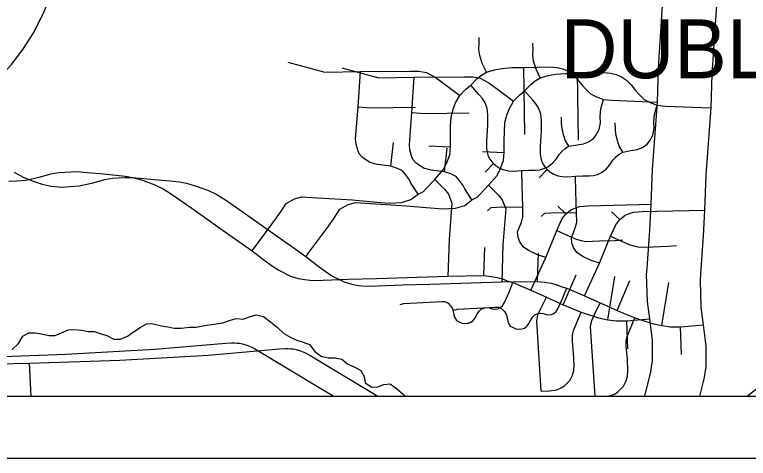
# Model space of a CAD drawing. Extents: x -38.2 to 41.9, y -4 to 24.9.
# Drawn here: x 3.113 to 4.294, y 14 to 14.713 of the extents above; entities that cross this region are included whole.
import ezdxf

# ---------------------------------------------------------------- set-up
doc = ezdxf.new("R2010")
doc.units = 0
for name, color, linetype in [('Default', 7, 'Continuous'), ('GM_X_City_Street', 7, 'Continuous'), ('GM_X_Corporation_Text', 7, 'Continuous'), ('GM_X_County_Road', 7, 'Continuous'), ('GM_X_Interchange_Ramps', 7, 'Continuous'), ('GM_X_Interstate_Location', 7, 'Continuous'), ('GM_X_Minor_River', 7, 'Continuous'), ('SH_Cut_Line', 7, 'Continuous'), ('SH_Data', 7, 'Continuous')]:
    doc.layers.add(name, color=color, linetype=linetype)

msp = doc.modelspace()

# ---------------------------------------------------------------- linework, layer by layer
at = {"layer": 'Default'}
msp.add_lwpolyline([(2.1, 17.1909), (2.1, 14.1), (6.3118, 14.1)], dxfattribs=at)
at = {"layer": 'GM_X_City_Street'}
for p, q in [((3.934, 14.5205), (3.9323, 14.6282)), ((3.7184, 14.4697), (3.7228, 14.5079)), ((3.7795, 14.5024), (3.8142, 14.5009)), ((3.9872, 14.4055), (4.0002, 14.3931)), ((3.8682, 14.2937), (3.8695, 14.3389)), ((3.996, 14.2468), (4.0166, 14.2951)), ((4.0678, 14.2229), (4.0791, 14.2921)), ((4.0998, 14.1763), (4.0983, 14.2208))]:
    msp.add_line(p, q, dxfattribs=at)
for points in [[(4.1308, 14.306), (4.1314, 14.3134), (4.1351, 14.3667), (4.1371, 14.4084), (4.1393, 14.4646), (4.1473, 14.5729), (4.1489, 14.6271), (4.1569, 14.7459), (4.1682, 14.9427)], [(3.8723, 14.6209), (3.8656, 14.6349), (3.8614, 14.6476), (3.8602, 14.6574), (3.8607, 14.6669), (3.8605, 14.6769)], [(3.4954, 14.3335), (3.5288, 14.3789), (3.5397, 14.394), (3.5502, 14.4096), (3.5635, 14.4171), (3.575, 14.4206), (3.5912, 14.4194), (3.6566, 14.4154), (3.6959, 14.4119), (3.7156, 14.4101), (3.7358, 14.4113), (3.7508, 14.4159), (3.7624, 14.4249), (3.7708, 14.4292), (3.7754, 14.4336), (3.7893, 14.4483), (3.8029, 14.4639), (3.8078, 14.4741), (3.8133, 14.4879), (3.8142, 14.5009), (3.8142, 14.5206), (3.8146, 14.5335), (3.8155, 14.5492), (3.8175, 14.5572), (3.8191, 14.5628), (3.8227, 14.5718), (3.8295, 14.5835), (3.8388, 14.5929), (3.8472, 14.6002), (3.8572, 14.6105), (3.8643, 14.616), (3.8723, 14.6209), (3.8853, 14.6246), (3.8968, 14.627), (3.913, 14.6282), (3.9323, 14.6282), (3.9751, 14.6293), (3.9859, 14.6283), (3.9946, 14.6265), (4.0032, 14.6228), (4.0113, 14.6172), (4.0184, 14.6098), (4.0259, 14.6005), (4.0324, 14.5934), (4.0398, 14.5862), (4.0494, 14.5813), (4.0605, 14.5772), (4.0735, 14.5757), (4.1473, 14.5729)], [(3.5529, 14.6372), (3.6125, 14.6209), (3.6697, 14.6221), (3.7498, 14.6227), (3.7637, 14.6227), (3.7757, 14.6203), (3.7896, 14.6131), (3.8058, 14.6011), (3.8295, 14.5835)], [(3.7624, 14.4249), (3.7508, 14.4425), (3.7485, 14.4477), (3.7422, 14.4564), (3.7372, 14.4625), (3.7294, 14.4662), (3.7184, 14.4697), (3.6968, 14.4723), (3.6846, 14.4755), (3.6728, 14.4839), (3.6676, 14.4897), (3.6652, 14.4954), (3.6624, 14.505), (3.6618, 14.5131), (3.6658, 14.5651), (3.6697, 14.6221)], [(3.8835, 14.4738), (3.8775, 14.4814), (3.8757, 14.4853), (3.8743, 14.4899), (3.8727, 14.4984), (3.8727, 14.5102), (3.8746, 14.5364), (3.8746, 14.5523), (3.8732, 14.5626), (3.87, 14.5717), (3.8659, 14.5785), (3.8602, 14.5852), (3.8472, 14.6002)], [(3.8704, 14.46), (3.8835, 14.4738), (3.8877, 14.4701), (3.8944, 14.4662), (3.9007, 14.4636), (3.9079, 14.4623), (3.9159, 14.4619), (3.9292, 14.4628), (3.9407, 14.4633), (3.9508, 14.4634), (3.958, 14.4641), (3.9645, 14.4658), (3.9709, 14.4685), (3.9785, 14.4744), (3.9844, 14.4812), (3.9892, 14.4884), (3.9935, 14.4936), (3.9992, 14.4983), (4.0051, 14.5017), (4.0181, 14.5038), (4.0283, 14.5057), (4.0367, 14.5088), (4.0444, 14.5144), (4.0485, 14.5193), (4.0534, 14.5286), (4.0559, 14.5395), (4.0553, 14.5497), (4.0562, 14.5618), (4.0605, 14.5772)], [(3.6658, 14.5651), (3.6866, 14.5634), (3.7581, 14.5646)], [(4.0051, 14.5017), (3.9992, 14.5113), (3.9964, 14.5203), (3.9943, 14.5302), (3.9933, 14.5382), (3.993, 14.5484)], [(3.104, 14.4454), (3.1155, 14.4462), (3.1312, 14.4472), (3.1525, 14.452), (3.1721, 14.4573), (3.1838, 14.4594), (3.2043, 14.4608), (3.2144, 14.461), (3.2294, 14.4598), (3.251, 14.4577), (3.2767, 14.4554), (3.2911, 14.4538), (3.3032, 14.4515), (3.3186, 14.447), (3.3386, 14.4398), (3.3519, 14.4334), (3.3657, 14.4248), (3.398, 14.4022), (3.4473, 14.3675), (3.4687, 14.3525), (3.4954, 14.3335), (3.5164, 14.3173), (3.5265, 14.3101), (3.5382, 14.3023), (3.5569, 14.293), (3.5692, 14.2893), (3.5799, 14.2873), (3.5925, 14.2861), (3.6097, 14.2865), (3.65, 14.2881), (3.6955, 14.2891), (3.8104, 14.2928), (3.8682, 14.2937), (3.8799, 14.2926), (3.8897, 14.2908), (3.8982, 14.2886), (3.9057, 14.2855), (3.915, 14.2829), (3.9436, 14.2702), (3.9687, 14.2592), (3.996, 14.2468), (4.0245, 14.2349), (4.0526, 14.226), (4.0678, 14.2229), (4.0815, 14.2208), (4.0983, 14.2208), (4.1353, 14.2241)], [(3.9679, 14.3228), (3.9543, 14.3272), (3.9398, 14.334), (3.9314, 14.3402), (3.9258, 14.3482), (3.9233, 14.3553), (3.9224, 14.364), (3.9252, 14.3705), (3.9286, 14.3798), (3.9311, 14.3885), (3.9308, 14.4046), (3.9298, 14.4387), (3.9292, 14.4628)], [(3.7893, 14.4483), (3.8046, 14.433), (3.811, 14.4246), (3.8168, 14.4102), (3.8124, 14.3525), (3.8104, 14.2928)], [(3.8741, 14.3978), (3.8797, 14.4033), (3.8893, 14.4037), (3.9308, 14.4046)], [(3.9436, 14.2702), (3.9679, 14.3228), (3.9856, 14.3665), (3.9938, 14.3848), (4.0002, 14.3931), (4.0092, 14.4001), (4.0144, 14.4024), (4.0222, 14.405), (4.0357, 14.4059), (4.1371, 14.4084)], [(3.9856, 14.3665), (4.0042, 14.3578), (4.0166, 14.3522), (4.0246, 14.3501), (4.0324, 14.3488), (4.0534, 14.3495), (4.0782, 14.3501), (4.0915, 14.3513)], [(4.1269, 14.1), (4.1367, 14.139), (4.1394, 14.1573), (4.1394, 14.1893), (4.1353, 14.2241), (4.1312, 14.2523), (4.13, 14.2953), (4.1308, 14.306)], [(3.7333, 14.2472), (3.7393, 14.2489), (3.8003, 14.2522), (3.8055, 14.252), (3.8106, 14.2496), (3.8147, 14.2453), (3.8175, 14.241), (3.8195, 14.2328), (3.8209, 14.227), (3.8243, 14.2218), (3.8286, 14.2196), (3.8333, 14.2173), (3.8383, 14.2169), (3.8429, 14.2172), (3.8472, 14.2187), (3.851, 14.2215), (3.854, 14.2258), (3.8574, 14.2318), (3.8606, 14.2367), (3.8637, 14.2397), (3.8674, 14.2415), (3.8717, 14.2424), (3.8768, 14.2418), (3.8822, 14.2404), (3.8861, 14.24), (3.8906, 14.2406), (3.8943, 14.2423), (3.8981, 14.2454), (3.9012, 14.2506), (3.9087, 14.267), (3.915, 14.2829)], [(3.9606, 14.1079), (3.9531, 14.2212), (3.9551, 14.2305), (3.9596, 14.2407), (3.9687, 14.2592)], [(3.9606, 14.1079), (3.974, 14.1085), (3.9857, 14.1101), (3.9927, 14.1131), (3.9978, 14.1166), (4.0063, 14.1251), (4.0108, 14.1337), (4.013, 14.1413), (4.0133, 14.1499), (4.0125, 14.1684), (4.0106, 14.189), (4.0106, 14.198), (4.0121, 14.2053), (4.0245, 14.2349)], [(3.0504, 14.162), (3.1957, 14.1672), (3.3387, 14.1753), (3.4529, 14.1852), (3.462, 14.1858), (3.467, 14.1856), (3.4706, 14.1853), (3.4747, 14.185), (3.4795, 14.1841), (3.4866, 14.182), (3.4946, 14.1788), (3.5005, 14.1757), (3.6058, 14.1125), (3.6239, 14.1015), (3.6259, 14.1)], [(4.2918, 14.1), (4.3333, 14.1325)]]:
    msp.add_lwpolyline(points, dxfattribs=at)
at = {"layer": 'GM_X_County_Road'}
msp.add_lwpolyline([(2.1, 17.2471), (2.1, 14.1), (6.3987, 14.1)], dxfattribs=at)
at = {"layer": 'GM_X_Interchange_Ramps'}
for points in [[(4.4315, 16.4679), (4.2738, 16.48), (4.1951, 16.4857), (4.1257, 16.4908), (3.9778, 16.5019), (3.9238, 16.5054), (3.9086, 16.5077), (3.8908, 16.5049), (3.8743, 16.4969), (3.471, 16.5538), (3.1389, 16.5821), (3.0621, 16.5852), (2.8019, 16.6115), (2.5228, 16.6342), (2.1521, 16.6664), (2.1328, 15.831), (2.1334, 15.4951), (2.1335, 15.4167), (2.1303, 14.1722), (2.1303, 14.1626), (2.1, 14.1636), (2.1, 14.1), (6.3126, 14.1)], [(4.3603, 16.4708), (4.2816, 16.4765), (4.2121, 16.4816), (4.0643, 16.4927), (4.0103, 16.4962), (3.9951, 16.4985), (3.9773, 16.4958), (3.9608, 16.4877), (3.5575, 16.5447), (3.2254, 16.5729), (3.1485, 16.5761), (2.8884, 16.6024), (2.6092, 16.625), (2.2386, 16.6572), (2.2193, 15.8218), (2.2199, 15.4859), (2.22, 15.4075), (2.2168, 14.163), (2.2168, 14.1534), (2.1, 14.1575), (2.1, 14.1), (6.3995, 14.1)]]:
    msp.add_lwpolyline(points, dxfattribs=at)
at = {"layer": 'GM_X_Interstate_Location'}
for p, q in [((4.0205, 14.5113), (4.0188, 14.619)), ((3.8049, 14.4605), (3.8093, 14.4987)), ((3.8659, 14.4932), (3.9006, 14.4918)), ((4.0736, 14.3963), (4.0867, 14.3839)), ((3.9547, 14.2845), (3.9559, 14.3297)), ((4.0825, 14.2376), (4.1031, 14.2859)), ((4.1543, 14.2137), (4.1655, 14.2829)), ((4.1863, 14.1671), (4.1847, 14.2116)), ((3.1398, 14.1), (3.1369, 14.1529))]:
    msp.add_line(p, q, dxfattribs=at)
for points in [[(2.8264, 14.3738), (2.9006, 14.445), (2.9656, 14.5007), (3.0166, 14.5437), (3.0643, 14.5883), (3.0816, 14.6047), (3.1079, 14.633), (3.1263, 14.6573), (3.144, 14.6848), (3.1605, 14.7186), (3.1752, 14.7558), (3.1846, 14.7903), (3.1941, 14.8408), (3.2113, 14.9302), (3.2281, 15.037), (3.231, 15.0671), (3.2298, 15.0989), (3.2263, 15.1293), (3.2225, 15.1483)], [(4.2173, 14.2968), (4.2179, 14.3042), (4.2215, 14.3575), (4.2236, 14.3992), (4.2258, 14.4554), (4.2337, 14.5637), (4.2354, 14.6179), (4.2433, 14.7367), (4.2546, 14.9335)], [(3.9588, 14.6117), (3.9521, 14.6258), (3.9479, 14.6385), (3.9467, 14.6483), (3.9472, 14.6577), (3.947, 14.6677)], [(3.6394, 14.628), (3.699, 14.6118), (3.7562, 14.613), (3.8363, 14.6136), (3.8502, 14.6136), (3.8622, 14.6111), (3.876, 14.6039), (3.8923, 14.5919), (3.916, 14.5743)], [(3.5819, 14.3244), (3.6152, 14.3697), (3.6262, 14.3848), (3.6366, 14.4004), (3.6499, 14.4079), (3.6615, 14.4114), (3.6777, 14.4102), (3.743, 14.4062), (3.7824, 14.4027), (3.802, 14.401), (3.8223, 14.4021), (3.8373, 14.4067), (3.8489, 14.4157), (3.8573, 14.42), (3.8619, 14.4244), (3.8758, 14.4391), (3.8894, 14.4547), (3.8943, 14.4649), (3.8998, 14.4787), (3.9006, 14.4918), (3.9006, 14.5114), (3.9011, 14.5243), (3.9019, 14.54), (3.904, 14.548), (3.9056, 14.5536), (3.9092, 14.5626), (3.916, 14.5743), (3.9253, 14.5837), (3.9337, 14.591), (3.9436, 14.6013), (3.9508, 14.6068), (3.9588, 14.6117), (3.9718, 14.6154), (3.9832, 14.6178), (3.9995, 14.619), (4.0188, 14.619), (4.0615, 14.6201), (4.0724, 14.6192), (4.0811, 14.6173), (4.0897, 14.6136), (4.0978, 14.608), (4.1049, 14.6006), (4.1123, 14.5913), (4.1188, 14.5842), (4.1263, 14.577), (4.1359, 14.5721), (4.147, 14.5681), (4.16, 14.5665), (4.2337, 14.5637)], [(3.8489, 14.4157), (3.8373, 14.4333), (3.835, 14.4385), (3.8286, 14.4472), (3.8237, 14.4533), (3.8159, 14.4571), (3.8049, 14.4605), (3.7832, 14.4631), (3.7711, 14.4663), (3.7592, 14.4747), (3.754, 14.4805), (3.7517, 14.4863), (3.7488, 14.4958), (3.7483, 14.5039), (3.7523, 14.5559), (3.7562, 14.613)], [(3.97, 14.4646), (3.964, 14.4722), (3.9621, 14.4761), (3.9608, 14.4807), (3.9592, 14.4892), (3.9592, 14.501), (3.9611, 14.5272), (3.9611, 14.5431), (3.9597, 14.5534), (3.9565, 14.5625), (3.9524, 14.5693), (3.9467, 14.576), (3.9337, 14.591)], [(3.9569, 14.4508), (3.97, 14.4646), (3.9742, 14.4609), (3.9809, 14.457), (3.9872, 14.4544), (3.9943, 14.4532), (4.0024, 14.4527), (4.0157, 14.4536), (4.0272, 14.4541), (4.0372, 14.4542), (4.0445, 14.4549), (4.051, 14.4566), (4.0574, 14.4594), (4.0649, 14.4652), (4.0708, 14.472), (4.0756, 14.4792), (4.08, 14.4844), (4.0857, 14.4891), (4.0916, 14.4925), (4.1046, 14.4947), (4.1148, 14.4965), (4.1232, 14.4996), (4.1309, 14.5052), (4.1349, 14.5101), (4.1399, 14.5194), (4.1424, 14.5303), (4.1418, 14.5405), (4.1427, 14.5526), (4.147, 14.5681)], [(3.7523, 14.5559), (3.7731, 14.5542), (3.8445, 14.5554)], [(4.0916, 14.4925), (4.0857, 14.5021), (4.0829, 14.5111), (4.0807, 14.521), (4.0798, 14.529), (4.0795, 14.5393)], [(3.1124, 14.46), (3.1266, 14.4522), (3.1412, 14.4461), (3.1572, 14.4407), (3.1718, 14.4378), (3.1829, 14.4364), (3.1905, 14.4362), (3.202, 14.437), (3.2176, 14.438), (3.239, 14.4428), (3.2585, 14.4481), (3.2703, 14.4502), (3.2908, 14.4516), (3.3009, 14.4518), (3.3159, 14.4506), (3.3375, 14.4485), (3.3632, 14.4463), (3.3776, 14.4446), (3.3897, 14.4424), (3.4051, 14.4378), (3.4251, 14.4306), (3.4384, 14.4243), (3.4522, 14.4156), (3.4845, 14.393), (3.5338, 14.3583), (3.5552, 14.3433), (3.5819, 14.3244), (3.6029, 14.3081), (3.613, 14.3009), (3.6247, 14.2931), (3.6434, 14.2839), (3.6557, 14.2802), (3.6664, 14.2781), (3.6789, 14.2769), (3.6962, 14.2773), (3.7365, 14.2789), (3.7819, 14.2799), (3.8969, 14.2836), (3.9547, 14.2845), (3.9664, 14.2834), (3.9762, 14.2816), (3.9847, 14.2794), (3.9922, 14.2763), (4.0014, 14.2737), (4.0301, 14.261), (4.0552, 14.25), (4.0825, 14.2376), (4.1109, 14.2257), (4.139, 14.2168), (4.1543, 14.2137), (4.168, 14.2116), (4.1847, 14.2116), (4.2218, 14.2149)], [(4.0544, 14.3136), (4.0408, 14.318), (4.0262, 14.3248), (4.0179, 14.331), (4.0123, 14.339), (4.0098, 14.3462), (4.0089, 14.3548), (4.0117, 14.3613), (4.0151, 14.3706), (4.0176, 14.3793), (4.0173, 14.3954), (4.0163, 14.4295), (4.0157, 14.4536)], [(3.8758, 14.4391), (3.8911, 14.4238), (3.8975, 14.4154), (3.9033, 14.401), (3.8989, 14.3433), (3.8969, 14.2836)], [(3.9606, 14.3886), (3.9662, 14.3942), (3.9758, 14.3945), (4.0173, 14.3954)], [(4.0301, 14.261), (4.0544, 14.3136), (4.0721, 14.3573), (4.0803, 14.3756), (4.0867, 14.3839), (4.0956, 14.391), (4.1009, 14.3932), (4.1087, 14.3958), (4.1222, 14.3967), (4.2236, 14.3992)], [(4.0721, 14.3573), (4.0907, 14.3486), (4.103, 14.3431), (4.1111, 14.3409), (4.1188, 14.3397), (4.1399, 14.3403), (4.1647, 14.3409), (4.178, 14.3421)], [(4.2157, 14.1), (4.2231, 14.1298), (4.2259, 14.1481), (4.2259, 14.1802), (4.2218, 14.2149), (4.2176, 14.2431), (4.2165, 14.2861), (4.2173, 14.2968)], [(3.8198, 14.238), (3.8258, 14.2397), (3.8867, 14.243), (3.892, 14.2428), (3.8971, 14.2404), (3.9011, 14.2361), (3.904, 14.2318), (3.9059, 14.2236), (3.9074, 14.2179), (3.9107, 14.2126), (3.9151, 14.2104), (3.9198, 14.2081), (3.9248, 14.2077), (3.9293, 14.208), (3.9337, 14.2095), (3.9375, 14.2123), (3.9405, 14.2166), (3.9438, 14.2226), (3.9471, 14.2275), (3.9501, 14.2305), (3.9538, 14.2323), (3.9582, 14.2333), (3.9633, 14.2326), (3.9687, 14.2312), (3.9726, 14.2309), (3.9771, 14.2314), (3.9807, 14.2331), (3.9846, 14.2362), (3.9877, 14.2414), (3.9952, 14.2578), (4.0014, 14.2737)], [(4.047, 14.1), (4.0396, 14.212), (4.0416, 14.2214), (4.0461, 14.2315), (4.0552, 14.25)], [(4.0656, 14.1), (4.0722, 14.101), (4.0792, 14.1039), (4.0843, 14.1074), (4.0927, 14.1159), (4.0973, 14.1245), (4.0995, 14.1321), (4.0998, 14.1407), (4.099, 14.1592), (4.0971, 14.1798), (4.0971, 14.1888), (4.0985, 14.1961), (4.1109, 14.2257)], [(3.0077, 14.1503), (3.1369, 14.1529), (3.2822, 14.158), (3.4252, 14.1661), (3.5394, 14.176), (3.5485, 14.1766), (3.5535, 14.1764), (3.5571, 14.1761), (3.5612, 14.1758), (3.566, 14.1749), (3.573, 14.1729), (3.581, 14.1696), (3.587, 14.1665), (3.6922, 14.1033), (3.6976, 14.1)]]:
    msp.add_lwpolyline(points, dxfattribs=at)
at = {"layer": 'GM_X_Minor_River'}
for points in [[(3.199, 14.2065), (3.2085, 14.2071), (3.2209, 14.2058), (3.2311, 14.2041), (3.241, 14.204), (3.2508, 14.2008), (3.2617, 14.1973), (3.2727, 14.1914), (3.2833, 14.1917), (3.2947, 14.1965), (3.3046, 14.2035), (3.3153, 14.2102), (3.3264, 14.2166), (3.3362, 14.216), (3.3495, 14.2128), (3.3597, 14.2116), (3.3699, 14.2095), (3.3812, 14.2094), (3.3945, 14.2111), (3.4051, 14.211), (3.4158, 14.2131), (3.4264, 14.2145), (3.4374, 14.2162), (3.448, 14.2176), (3.4602, 14.2224), (3.4697, 14.2249), (3.4807, 14.2236), (3.491, 14.2273), (3.502, 14.2306), (3.5137, 14.2281), (3.525, 14.2196), (3.5358, 14.2108), (3.5463, 14.2007), (3.5576, 14.1941), (3.5674, 14.1902), (3.5772, 14.187), (3.5874, 14.1831), (3.5963, 14.172), (3.6061, 14.1643), (3.6178, 14.1618), (3.6288, 14.1617), (3.6397, 14.1596), (3.6495, 14.1515), (3.6604, 14.1468), (3.6702, 14.1414), (3.6758, 14.1318), (3.6771, 14.1216), (3.6877, 14.1146), (3.6975, 14.1152), (3.707, 14.1185), (3.7176, 14.1199), (3.7274, 14.1125), (3.739, 14.1025), (3.7415, 14.1)], [(3.1092, 14.175), (3.1195, 14.1847), (3.1265, 14.1964), (3.136, 14.202), (3.1463, 14.2018), (3.1565, 14.2002), (3.1682, 14.1974), (3.1776, 14.1976), (3.1872, 14.2013), (3.199, 14.2065)]]:
    msp.add_lwpolyline(points, dxfattribs=at)
at = {"layer": 'SH_Cut_Line'}
msp.add_lwpolyline([(4.4315, 16.4679), (4.2738, 16.48), (4.1951, 16.4857), (4.1257, 16.4908), (3.9778, 16.5019), (3.9238, 16.5054), (3.9086, 16.5077), (3.8908, 16.5049), (3.8743, 16.4969), (3.471, 16.5538), (3.1389, 16.5821), (3.0621, 16.5852), (2.8019, 16.6115), (2.5228, 16.6342), (2.1521, 16.6664), (2.1328, 15.831), (2.1334, 15.4951), (2.1335, 15.4167), (2.1303, 14.1722), (2.1303, 14.1626), (2.1, 14.1636), (2.1, 14.1), (8.9, 14.1)], dxfattribs=at)
at = {"layer": 'SH_Data'}
for p, q in [((2.1, 14.1), (8.9, 14.1)), ((2, 14), (9, 14))]:
    msp.add_line(p, q, dxfattribs=at)

# ---------------------------------------------------------------- texts
at = {"layer": 'GM_X_Corporation_Text'}
msp.add_text('DUBLIN', height=0.0947, rotation=0, dxfattribs=at).set_placement((3.9916, 14.6111))

doc.saveas('drawing.dxf')
